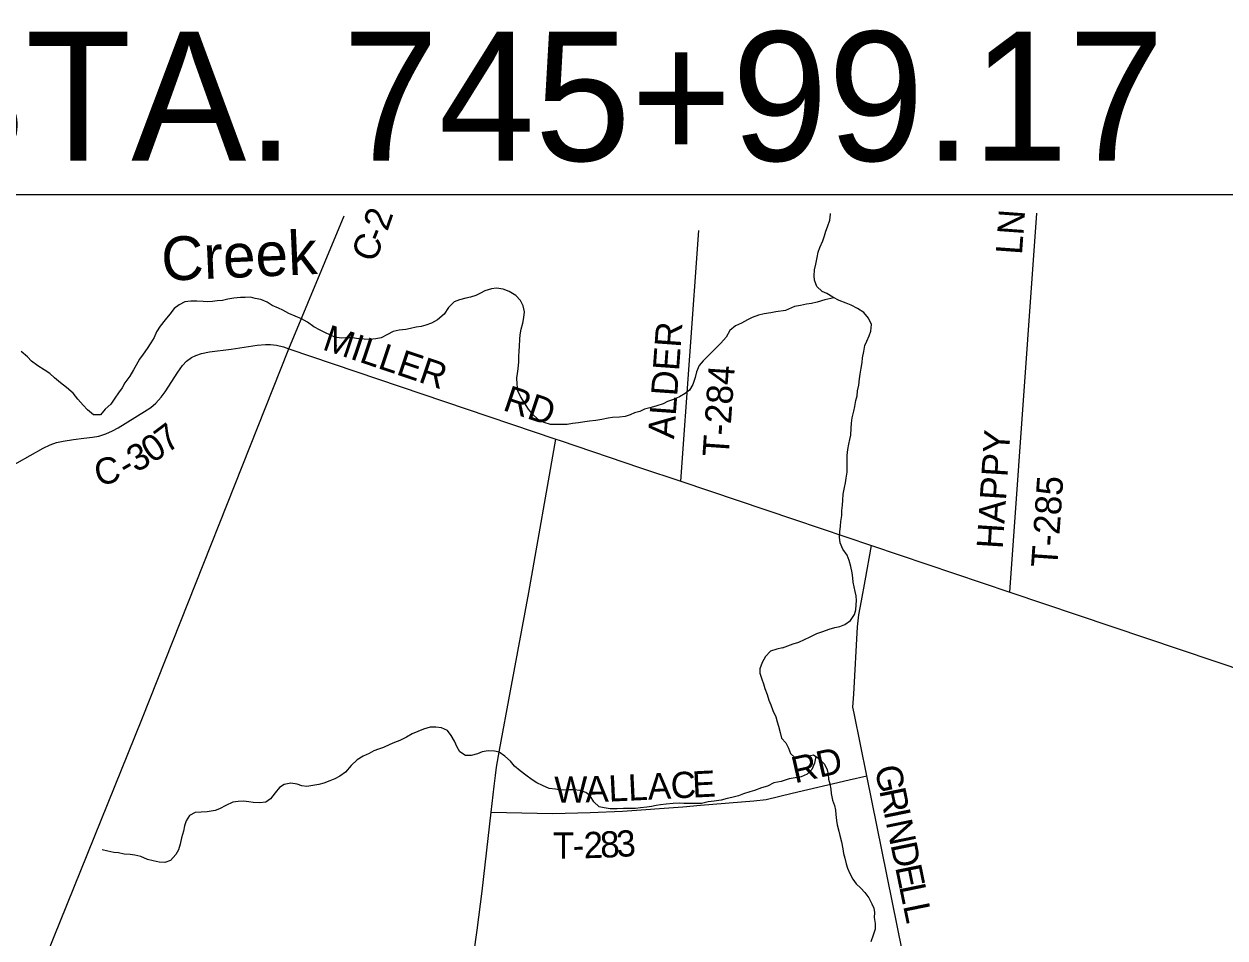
# Model space of a CAD drawing. Extents: x 0 to 34, y 0 to 22.
# Drawn here: x 6.445 to 7.746, y 18.883 to 19.874 of the extents above; entities that cross this region are included whole.
import ezdxf

# ---------------------------------------------------------------- set-up
doc = ezdxf.new("R2010")
doc.units = 0
for name, color, linetype in [('GM_X_County_Road', 7, 'Continuous'), ('GM_X_County_Road_Text', 7, 'Continuous'), ('GM_X_Minor_River', 7, 'Continuous'), ('GM_X_Minor_River_Text', 7, 'Continuous'), ('GM_X_Township_Road', 7, 'Continuous'), ('GM_X_Township_Road_Text', 7, 'Continuous'), ('SH_Text', 7, 'Continuous')]:
    doc.layers.add(name, color=color, linetype=linetype)

msp = doc.modelspace()

# ---------------------------------------------------------------- linework, layer by layer
at = {"layer": 'GM_X_County_Road'}
for points in [[(6.3004, 18.376), (6.3047, 18.3928), (6.3073, 18.4041), (6.3232, 18.4893), (6.3256, 18.5003), (6.3282, 18.5101), (6.3329, 18.523), (6.3382, 18.5363), (6.4625, 18.8471), (6.5726, 19.1199), (6.732, 19.5215), (6.7919, 19.6658)], [(6.3948, 19.3743), (6.4657, 19.4141), (6.4733, 19.4177), (6.4802, 19.4201), (6.4875, 19.4217), (6.4986, 19.4233), (6.5097, 19.4247), (6.519, 19.4259), (6.526, 19.427), (6.5337, 19.4294), (6.5409, 19.4327), (6.5469, 19.4361), (6.5756, 19.4537), (6.5823, 19.4582), (6.5877, 19.4629), (6.5935, 19.4693), (6.5977, 19.4751), (6.6116, 19.4962), (6.6168, 19.5034), (6.6211, 19.5082), (6.6265, 19.5122), (6.631, 19.5144), (6.6374, 19.5166), (6.6458, 19.5183), (6.6692, 19.5213), (6.6975, 19.5257), (6.7064, 19.5263), (6.712, 19.5264), (6.7185, 19.5255), (6.7259, 19.5237), (6.732, 19.5215), (7.0211, 19.4239), (7.0257, 19.4223)], [(7.0257, 19.4223), (7.0608, 19.4103), (7.1126, 19.3926), (7.1564, 19.3781), (7.2794, 19.3367), (7.3631, 19.3085), (7.5127, 19.2579), (7.8078, 19.1585)]]:
    msp.add_lwpolyline(points, dxfattribs=at)
at = {"layer": 'GM_X_Minor_River'}
for points in [[(7.2666, 19.1978), (7.278, 19.2019), (7.2843, 19.2039), (7.2905, 19.2065), (7.2966, 19.2097), (7.3038, 19.2131), (7.3103, 19.2154), (7.3171, 19.2178), (7.3233, 19.2195), (7.3286, 19.2206), (7.334, 19.2229), (7.3404, 19.2272), (7.3444, 19.2338), (7.346, 19.2388), (7.3464, 19.2443), (7.3466, 19.249), (7.3462, 19.2538), (7.3453, 19.2585), (7.3441, 19.2638), (7.3432, 19.2686), (7.3427, 19.2735), (7.3421, 19.2788), (7.3406, 19.2857), (7.3388, 19.2923), (7.3367, 19.2982), (7.3318, 19.3045), (7.3292, 19.3113), (7.3284, 19.3176), (7.3288, 19.3235), (7.3294, 19.3293), (7.3298, 19.3347), (7.3308, 19.3411), (7.331, 19.3466), (7.3314, 19.3523), (7.3318, 19.3578), (7.3324, 19.3642), (7.3337, 19.3713), (7.3349, 19.3766), (7.3357, 19.3813), (7.3366, 19.388), (7.3368, 19.3931), (7.3367, 19.4001), (7.3367, 19.406), (7.3373, 19.4126), (7.3383, 19.4183), (7.3394, 19.4234), (7.3406, 19.4282), (7.3408, 19.4358), (7.3414, 19.4409), (7.342, 19.4468), (7.3437, 19.4542), (7.345, 19.4593), (7.346, 19.4657), (7.3473, 19.4706), (7.3477, 19.476), (7.3491, 19.4824), (7.3501, 19.489), (7.3508, 19.494), (7.3518, 19.5008), (7.3528, 19.5067), (7.3532, 19.5118), (7.3547, 19.5186), (7.3559, 19.5251), (7.358, 19.53), (7.3603, 19.5357), (7.3622, 19.5406), (7.363, 19.548), (7.3596, 19.5549), (7.3547, 19.5609), (7.3477, 19.5655), (7.3409, 19.5688), (7.3354, 19.5711), (7.3278, 19.574), (7.3212, 19.5776), (7.3146, 19.5816), (7.3097, 19.5839), (7.3036, 19.5892), (7.3012, 19.5959), (7.3008, 19.6006), (7.3014, 19.6071), (7.3026, 19.6135), (7.3041, 19.6207), (7.3053, 19.6264), (7.307, 19.6314), (7.3102, 19.6387), (7.312, 19.6439), (7.3135, 19.649), (7.3152, 19.6539), (7.3177, 19.6609), (7.3187, 19.6674), (7.3187, 19.6683)], [(7.27, 19.5631), (7.2595, 19.5619), (7.254, 19.5608), (7.2466, 19.5595), (7.2404, 19.558), (7.2338, 19.5556), (7.2286, 19.553), (7.2222, 19.5494), (7.2158, 19.5466), (7.2097, 19.5415), (7.2055, 19.5343), (7.1996, 19.5279), (7.1931, 19.5211), (7.1869, 19.5147), (7.1808, 19.5087), (7.1762, 19.5036), (7.1735, 19.4968), (7.1718, 19.4905), (7.1695, 19.483), (7.1659, 19.4767), (7.1611, 19.4733), (7.1551, 19.4696), (7.1484, 19.4668), (7.142, 19.4644), (7.1372, 19.4621), (7.1306, 19.4599), (7.1242, 19.4582), (7.1172, 19.4562), (7.1121, 19.4539), (7.1062, 19.4521), (7.1015, 19.4502), (7.096, 19.4484), (7.0901, 19.4476), (7.0825, 19.4471), (7.0776, 19.4464), (7.0708, 19.4449), (7.0644, 19.4438), (7.0574, 19.4431), (7.0523, 19.4424), (7.0457, 19.4415), (7.0392, 19.4406), (7.0332, 19.4397), (7.0271, 19.4395), (7.0213, 19.4395), (7.0152, 19.4398), (7.0084, 19.4417), (7.0033, 19.4438), (6.9969, 19.4498), (6.9915, 19.4561), (6.9829, 19.4698), (6.9799, 19.476), (6.979, 19.4833), (6.9788, 19.4901), (6.9794, 19.4948), (6.9804, 19.4999), (6.9808, 19.5077), (6.9808, 19.5128), (6.9814, 19.5193), (6.9817, 19.5242), (6.9819, 19.5322), (6.9825, 19.5369), (6.9835, 19.543), (6.9852, 19.5494), (6.9864, 19.5557), (6.987, 19.5617), (6.9857, 19.5684), (6.9829, 19.5741), (6.9778, 19.5795), (6.9706, 19.5839), (6.964, 19.5864), (6.9569, 19.5872), (6.9512, 19.5868), (6.944, 19.5846), (6.9393, 19.582), (6.9345, 19.5795), (6.9285, 19.5775), (6.9235, 19.5764), (6.9167, 19.5747), (6.9109, 19.5727), (6.9048, 19.5665), (6.9002, 19.5591), (6.893, 19.5529), (6.8864, 19.5493), (6.8801, 19.5471), (6.875, 19.546), (6.8697, 19.5451), (6.8638, 19.5436), (6.8587, 19.5427), (6.8515, 19.542), (6.8449, 19.5403), (6.8387, 19.5371), (6.832, 19.5337), (6.8262, 19.5324), (6.8194, 19.5317), (6.8135, 19.532), (6.8076, 19.5326), (6.8003, 19.5336), (6.7935, 19.5334), (6.7884, 19.5333), (6.7818, 19.5341), (6.7769, 19.5364)], [(6.7769, 19.5364), (6.7708, 19.5394), (6.7659, 19.5418), (6.759, 19.5454), (6.7522, 19.5506), (6.7454, 19.554), (6.7386, 19.5571), (6.732, 19.56), (6.7254, 19.5635), (6.7205, 19.5656), (6.7137, 19.5687), (6.7083, 19.5721), (6.7015, 19.5752), (6.6952, 19.576), (6.6903, 19.5775), (6.6847, 19.5774), (6.6796, 19.5772), (6.6724, 19.5767), (6.6659, 19.5754), (6.6599, 19.5739), (6.6542, 19.5736), (6.6493, 19.5731), (6.6442, 19.5727), (6.6389, 19.5731), (6.6321, 19.5732), (6.6257, 19.5734), (6.6191, 19.5725), (6.6132, 19.5693), (6.6077, 19.5652), (6.6031, 19.5591), (6.598, 19.5529), (6.5925, 19.5463), (6.5884, 19.5401), (6.5858, 19.534), (6.5823, 19.5282), (6.5785, 19.5221), (6.5741, 19.5157), (6.5701, 19.5104), (6.5665, 19.5038), (6.5637, 19.4987), (6.5595, 19.4921), (6.5543, 19.4847), (6.5513, 19.4794), (6.5475, 19.4738), (6.5435, 19.4683), (6.5391, 19.4617), (6.533, 19.4562), (6.5277, 19.4502), (6.5203, 19.4502), (6.5139, 19.4556), (6.509, 19.4605), (6.5032, 19.4672), (6.4983, 19.4735), (6.491, 19.4798), (6.4844, 19.4848), (6.478, 19.4901), (6.4729, 19.4949), (6.4669, 19.4989), (6.4599, 19.5032), (6.4531, 19.5083), (6.4488, 19.5131), (6.442, 19.5186)], [(7.3223, 19.577), (7.3125, 19.5746), (7.3043, 19.5723), (7.2979, 19.5709), (7.2926, 19.5699), (7.2859, 19.5686), (7.2797, 19.5675), (7.27, 19.5631)], [(7.2666, 19.1978), (7.2603, 19.1963), (7.2537, 19.1941), (7.248, 19.1884), (7.2446, 19.1816), (7.2419, 19.175), (7.242, 19.1701), (7.2441, 19.1636), (7.2461, 19.1585), (7.2474, 19.1537), (7.2498, 19.1472), (7.2519, 19.1408), (7.2538, 19.1358), (7.2562, 19.1296), (7.2592, 19.1229), (7.2608, 19.1174), (7.2621, 19.1126), (7.264, 19.106), (7.2656, 19.0999)], [(7.2652, 19.0529), (7.2572, 19.0514), (7.2504, 19.0477), (7.2438, 19.0458), (7.2364, 19.0432), (7.2313, 19.0417), (7.2243, 19.0395), (7.219, 19.0374), (7.2118, 19.0356), (7.2065, 19.0345), (7.2002, 19.0326), (7.1927, 19.0316), (7.1859, 19.0306), (7.1789, 19.0288), (7.1734, 19.029), (7.1664, 19.0289), (7.1598, 19.0291), (7.1547, 19.0293), (7.1483, 19.029), (7.1405, 19.0283), (7.1346, 19.0274), (7.1297, 19.0267), (7.1246, 19.0257), (7.1197, 19.025), (7.1127, 19.0241), (7.1074, 19.0234), (7.1008, 19.0236), (7.0944, 19.0235), (7.0874, 19.0233), (7.08, 19.0232), (7.0734, 19.0244), (7.0679, 19.0255), (7.0621, 19.0309), (7.0583, 19.0372), (7.0534, 19.041), (7.0474, 19.0431), (7.0404, 19.0439), (7.034, 19.0436), (7.0264, 19.0435), (7.0206, 19.0443), (7.0138, 19.0451), (7.0066, 19.0483), (7.0004, 19.0512), (6.9955, 19.0547), (6.9887, 19.0598), (6.9825, 19.0644), (6.9761, 19.0694), (6.9718, 19.0747), (6.9658, 19.0801), (6.9596, 19.0847), (6.9547, 19.0857), (6.9479, 19.0861), (6.9414, 19.085), (6.9361, 19.0827), (6.9295, 19.0809), (6.9233, 19.0809), (6.9169, 19.0851), (6.9141, 19.0899), (6.9114, 19.0964), (6.9075, 19.1028), (6.9038, 19.108), (6.8972, 19.1109), (6.8909, 19.1117), (6.8851, 19.1115), (6.8777, 19.1095), (6.8714, 19.1071), (6.8656, 19.1044), (6.8593, 19.1007), (6.8521, 19.0971), (6.8462, 19.0951), (6.8413, 19.0927), (6.8345, 19.0895), (6.8288, 19.0878), (6.8239, 19.0859), (6.8189, 19.0831), (6.8123, 19.0801), (6.8059, 19.0764), (6.7992, 19.0702), (6.7931, 19.063), (6.7869, 19.0585), (6.7817, 19.0557), (6.7764, 19.0536), (6.7698, 19.051), (6.7643, 19.0495), (6.7579, 19.0484), (6.7513, 19.0475), (6.746, 19.0481), (6.7409, 19.0499), (6.7339, 19.0509), (6.7267, 19.0496), (6.7218, 19.0464), (6.717, 19.0406), (6.7119, 19.0341), (6.7068, 19.0304), (6.7001, 19.0297), (6.6933, 19.0299), (6.6884, 19.0307), (6.6828, 19.0313), (6.6771, 19.031), (6.671, 19.0304), (6.6636, 19.0269)], [(7.2656, 19.0999), (7.2702, 19.0947), (7.273, 19.089), (7.2751, 19.0831), (7.2804, 19.0785), (7.2872, 19.0791), (7.2937, 19.0802), (7.3001, 19.0815), (7.3061, 19.0777), (7.3122, 19.0714), (7.315, 19.0655), (7.3159, 19.0602), (7.3165, 19.0554), (7.3178, 19.0503), (7.3191, 19.0444), (7.3193, 19.0397), (7.3209, 19.0324), (7.3228, 19.0266), (7.3239, 19.0216), (7.3245, 19.0169), (7.325, 19.0106), (7.3258, 19.0059), (7.3276, 18.999), (7.3288, 18.9943), (7.3304, 18.9873), (7.3319, 18.9797), (7.3327, 18.9747), (7.334, 18.9696), (7.3355, 18.9637), (7.3371, 18.9588), (7.3396, 18.9531), (7.3428, 18.947), (7.3462, 18.942), (7.3516, 18.9373), (7.3558, 18.9325), (7.3601, 18.9266), (7.3635, 18.9203), (7.3654, 18.9156), (7.3661, 18.9107), (7.3659, 18.9055), (7.367, 18.8989), (7.367, 18.8928), (7.3649, 18.8862), (7.3622, 18.8792)], [(7.3027, 19.0799), (7.3014, 19.0726), (7.2983, 19.0659), (7.2934, 19.0608), (7.2868, 19.058), (7.2803, 19.0567), (7.2739, 19.0556), (7.2652, 19.0529)], [(6.6636, 19.0269), (6.6568, 19.0231), (6.6519, 19.0213), (6.6434, 19.02), (6.6368, 19.0197), (6.6303, 19.0191), (6.6243, 19.0159), (6.6205, 19.0101), (6.6189, 19.0048), (6.6176, 18.9989), (6.6156, 18.9919), (6.6143, 18.9847), (6.6122, 18.9789), (6.6095, 18.9736), (6.6036, 18.9672), (6.5975, 18.9651), (6.5913, 18.9653), (6.5849, 18.9667), (6.5788, 18.9683), (6.5717, 18.9715), (6.5652, 18.9729), (6.56, 18.9735), (6.5535, 18.9741), (6.5473, 18.9753), (6.5424, 18.9759), (6.5358, 18.9773), (6.5297, 18.9786)]]:
    msp.add_lwpolyline(points, dxfattribs=at)
at = {"layer": 'GM_X_Township_Road'}
for p, q in [((7.5127, 19.2579), (7.542, 19.6685)), ((7.1564, 19.3781), (7.1761, 19.6498)), ((6.951, 19.0197), (7.001, 19.0185))]:
    msp.add_line(p, q, dxfattribs=at)
for points in [[(6.8934, 18.5988), (6.9181, 18.7659), (6.9358, 18.8916), (6.9414, 18.9341), (6.951, 19.0197), (6.9543, 19.0478), (6.9557, 19.0592), (6.9568, 19.0684), (6.9602, 19.0866), (6.9719, 19.1509), (6.9917, 19.2576), (7.0211, 19.4239)], [(7.4019, 18.8413), (7.3578, 19.0589), (7.3442, 19.1269), (7.3429, 19.1335), (7.3437, 19.1474), (7.3479, 19.2202), (7.3491, 19.2333), (7.3521, 19.2486), (7.356, 19.2702), (7.3631, 19.3085)], [(7.001, 19.0185), (7.0179, 19.0181), (7.0583, 19.019), (7.0934, 19.0206), (7.1587, 19.0255), (7.1778, 19.0271), (7.2357, 19.0319), (7.2489, 19.0334), (7.2769, 19.04), (7.3387, 19.0545), (7.3578, 19.0589)]]:
    msp.add_lwpolyline(points, dxfattribs=at)
at = {"layer": 'SH_Text'}
msp.add_lwpolyline([(8.1244, 20.0434), (8.1244, 19.6886), (6.3016, 19.6886), (6.3016, 20.3124), (8.1244, 20.3124), (8.1244, 20.053)], dxfattribs=at)

# ---------------------------------------------------------------- texts
at = {"layer": 'GM_X_County_Road_Text'}
for s, height, rotation, p in [('2', 0.0284, 71.3993, (6.8386, 19.6482)), ('C', 0.0284, 67.6978, (6.8247, 19.6139)), ('-', 0.0284, 68.1481, (6.8336, 19.6357)), ('MILLER', 0.02841, 341.3308, (6.7671, 19.5213)), ('RD', 0.02841, 341.4078, (6.9625, 19.4555)), ('7', 0.0284, 36.8396, (6.6, 19.4077)), ('0', 0.0284, 33.5734, (6.5839, 19.397)), ('3', 0.0284, 28.2363, (6.566, 19.3872)), ('C', 0.0284, 13.1909, (6.5249, 19.3727)), ('-', 0.0284, 30.2642, (6.5562, 19.3814))]:
    msp.add_text(s, height=height, rotation=rotation, dxfattribs=at).set_placement(p)
at = {"layer": 'GM_X_Minor_River_Text'}
msp.add_text('Creek', height=0.04735, rotation=2.5621, dxfattribs=at).set_placement((6.5947, 19.5952))
at = {"layer": 'GM_X_Township_Road_Text'}
for s, height, rotation, p in [('LN', 0.02841, 85.878, (7.5259, 19.6231)), ('ALDER', 0.02841, 85.871, (7.1491, 19.4235)), ('T-284', 0.02841, 86.0548, (7.2082, 19.4039)), ('HAPPY', 0.02841, 86.2143, (7.5051, 19.3043)), ('T-285', 0.02841, 86.0741, (7.5641, 19.2839)), ('RD', 0.02841, 12.8481, (7.28, 19.0507)), ('W', 0.0284, 0.4371, (7.0195, 19.0297)), ('A', 0.0284, 2.0796, (7.0533, 19.03)), ('L', 0.0284, 2.7751, (7.0787, 19.0309)), ('L', 0.0284, 2.7833, (7.0999, 19.0319)), ('A', 0.0284, 2.785, (7.1211, 19.033)), ('C', 0.0284, 2.7875, (7.1461, 19.0342)), ('E', 0.0284, 2.7824, (7.1694, 19.0353)), ('G', 0.0284, 281.6607, (7.3663, 19.0676)), ('R', 0.0284, 281.6605, (7.3713, 19.0431)), ('I', 0.0284, 281.6656, (7.3761, 19.0203)), ('N', 0.0284, 281.6607, (7.3784, 19.0088)), ('T', 0.0284, 0.1286, (7.0178, 18.9692)), ('2', 0.0284, 1.7871, (7.0516, 18.9695)), ('8', 0.0284, 2.6388, (7.0696, 18.97)), ('3', 0.0284, 2.9416, (7.0872, 18.9709)), ('-', 0.0284, 0.9474, (7.0395, 18.9693)), ('D', 0.0284, 281.6607, (7.3835, 18.9843)), ('E', 0.0284, 281.6639, (7.3885, 18.9599)), ('L', 0.0284, 281.6604, (7.3928, 18.9391)), ('L', 0.0284, 281.6604, (7.3971, 18.9182))]:
    msp.add_text(s, height=height, rotation=rotation, dxfattribs=at).set_placement(p)
at = {"layer": 'SH_Text'}
msp.add_text('STA. 745+99.17', height=0.14, dxfattribs=at).set_placement((6.3218, 19.7254))

doc.saveas('drawing.dxf')
